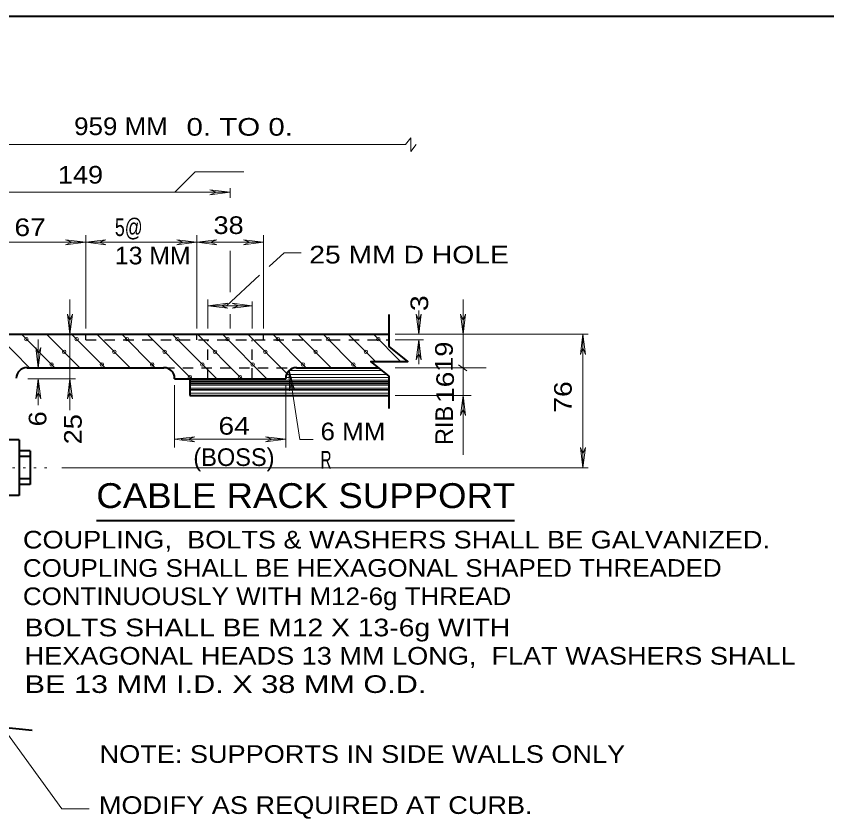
# Model space of a CAD drawing. Extents: x 312583 to 312854, y 144419 to 144597.
# Drawn here: x 312649.47 to 312684.42, y 144454.46 to 144489.05 of the extents above; entities that cross this region are included whole.
import ezdxf
from ezdxf.enums import TextEntityAlignment as Align

# ---------------------------------------------------------------- set-up
doc = ezdxf.new("R2010")
doc.units = 0
doc.header["$LTSCALE"] = 0.3
doc.header["$PDMODE"] = 32
doc.header["$PDSIZE"] = 0.15
doc.linetypes.add('DOTTED', pattern=[1.5, 0.3, -1.2])
doc.linetypes.add('SHORT_DASHED', pattern=[2.7, 1.5, -1.2])
doc.layers.add('1', color=7, linetype='Continuous', lineweight=13)

msp = doc.modelspace()

# ---------------------------------------------------------------- linework, layer by layer
at = {"layer": '1', "lineweight": 40}
for p, q in [((312629.3637, 144489.0473), (312702.1235, 144489.0473)), ((312647.438, 144475.3431), (312665.5544, 144475.3431)), ((312649.9297, 144473.9017), (312655.8407, 144473.9017)), ((312661.5524, 144473.9017), (312665.0867, 144473.9017)), ((312656.3007, 144473.4264), (312656.3007, 144473.4417)), ((312656.3007, 144473.4264), (312661.0924, 144473.4264)), ((312656.96, 144473.4264), (312656.96, 144472.7057)), ((312661.0924, 144473.4264), (312661.0924, 144473.4417)), ((312665.5544, 144472.1461), (312665.5544, 144473.5337)), ((312656.96, 144472.7057), (312665.5544, 144472.7057)), ((312649.5924, 144470.7891), (312649.1094, 144470.7891)), ((312649.5924, 144470.7891), (312649.5924, 144468.3971)), ((312650.0677, 144470.3137), (312649.5924, 144470.3137)), ((312650.0677, 144470.3137), (312650.0677, 144468.8724)), ((312650.0677, 144470.0684), (312649.5924, 144470.0684)), ((312650.0677, 144469.1101), (312649.5924, 144469.1101)), ((312650.0677, 144468.8724), (312649.5924, 144468.8724)), ((312649.5924, 144468.3971), (312649.1094, 144468.3971)), ((312652.935, 144467.3161), (312670.9517, 144467.3161)), ((312650.152, 144458.2617), (312645.9584, 144458.7064))]:
    msp.add_line(p, q, dxfattribs=at)
at = {"layer": '1'}
for p, q in [((312647.438, 144483.5157), (312666.2597, 144483.5157)), ((312657.19, 144482.3351), (312656.3084, 144481.4611)), ((312659.283, 144482.3351), (312657.19, 144482.3351)), ((312647.438, 144481.4611), (312658.6927, 144481.4611)), ((312657.8264, 144481.5684), (312658.1024, 144481.4611)), ((312658.6927, 144481.4611), (312657.8264, 144481.5684)), ((312657.8264, 144481.3537), (312658.1024, 144481.4611)), ((312658.6927, 144481.4611), (312657.8264, 144481.3537)), ((312658.6927, 144481.2157), (312658.6927, 144481.6451)), ((312651.601, 144479.4141), (312651.877, 144479.3067)), ((312652.4674, 144479.3067), (312651.601, 144479.4141)), ((312652.4674, 144475.5884), (312652.4674, 144479.6134)), ((312652.4674, 144479.3067), (312653.3337, 144479.4141)), ((312653.3337, 144479.4141), (312653.0577, 144479.3067)), ((312656.3927, 144479.4141), (312656.6687, 144479.3067)), ((312657.259, 144479.3067), (312656.3927, 144479.4141)), ((312657.259, 144475.5884), (312657.259, 144479.6134)), ((312657.259, 144479.3067), (312658.1254, 144479.4141)), ((312658.1254, 144479.4141), (312657.8494, 144479.3067)), ((312659.2677, 144479.4141), (312659.5437, 144479.3067)), ((312660.134, 144479.3067), (312659.2677, 144479.4141)), ((312660.134, 144475.5884), (312660.134, 144479.6134)), ((312651.601, 144479.1994), (312651.877, 144479.3067)), ((312652.4674, 144479.3067), (312651.601, 144479.1994)), ((312652.4674, 144479.3067), (312653.3337, 144479.1994)), ((312653.3337, 144479.1994), (312653.0577, 144479.3067)), ((312656.3927, 144479.1994), (312656.6687, 144479.3067)), ((312657.259, 144479.3067), (312656.3927, 144479.1994)), ((312657.259, 144479.3067), (312660.134, 144479.3067)), ((312657.259, 144479.3067), (312658.1254, 144479.1994)), ((312658.1254, 144479.1994), (312657.8494, 144479.3067)), ((312659.2677, 144479.1994), (312659.5437, 144479.3067)), ((312660.134, 144479.3067), (312659.2677, 144479.1994)), ((312658.6927, 144477.1524), (312658.6927, 144478.9387)), ((312661.0234, 144478.8544), (312660.3794, 144478.2641)), ((312661.7594, 144478.8544), (312661.0234, 144478.8544)), ((312659.9654, 144477.8884), (312658.5317, 144476.5697)), ((312651.785, 144472.0771), (312651.785, 144476.8373)), ((312657.7344, 144475.5884), (312657.7344, 144476.8457)), ((312657.7344, 144476.5697), (312658.6007, 144476.6771)), ((312657.7344, 144476.5697), (312659.651, 144476.5697)), ((312657.7344, 144476.5697), (312658.6007, 144476.4624)), ((312658.6007, 144476.6771), (312658.3247, 144476.5697)), ((312658.6007, 144476.4624), (312658.3247, 144476.5697)), ((312658.7847, 144476.6771), (312659.0607, 144476.5697)), ((312659.651, 144476.5697), (312658.7847, 144476.6771)), ((312658.7847, 144476.4624), (312659.0607, 144476.5697)), ((312659.651, 144476.5697), (312658.7847, 144476.4624)), ((312659.651, 144475.5884), (312659.651, 144476.7537)), ((312651.6777, 144476.2094), (312651.785, 144475.9334)), ((312651.785, 144475.3431), (312651.6777, 144476.2094)), ((312651.8924, 144476.2094), (312651.785, 144475.9334)), ((312651.785, 144475.3431), (312651.8924, 144476.2094)), ((312666.7197, 144476.2094), (312666.827, 144475.9334)), ((312666.827, 144475.3431), (312666.7197, 144476.2094)), ((312666.827, 144476.3704), (312666.827, 144475.3431)), ((312666.9344, 144476.2094), (312666.827, 144475.9334)), ((312666.827, 144475.3431), (312666.9344, 144476.2094)), ((312668.6364, 144476.2094), (312668.7437, 144475.9334)), ((312668.7437, 144475.3431), (312668.6364, 144476.2094)), ((312668.851, 144476.2094), (312668.7437, 144475.9334)), ((312668.7437, 144475.3431), (312668.851, 144476.2094)), ((312658.6927, 144475.5884), (312658.6927, 144476.2017)), ((312648.611, 144475.3431), (312650.0447, 144473.9017)), ((312649.692, 144475.3431), (312651.1334, 144473.9017)), ((312650.7807, 144475.3431), (312652.2144, 144473.9017)), ((312651.8617, 144475.3431), (312653.303, 144473.9017)), ((312652.9504, 144475.3431), (312654.384, 144473.9017)), ((312654.0314, 144475.3431), (312655.465, 144473.9017)), ((312655.1124, 144475.3431), (312657.029, 144473.4264)), ((312656.201, 144475.3431), (312658.1177, 144473.4264)), ((312657.282, 144475.3431), (312659.1987, 144473.4264)), ((312658.3707, 144475.3431), (312660.2797, 144473.4264)), ((312659.4517, 144475.3431), (312661.1384, 144473.6564)), ((312660.5327, 144475.3431), (312661.974, 144473.9017)), ((312661.6214, 144475.3431), (312663.055, 144473.9017)), ((312662.7024, 144475.3431), (312664.1437, 144473.9017)), ((312663.791, 144475.3431), (312664.964, 144474.1701)), ((312664.872, 144475.3431), (312666.045, 144474.1701)), ((312665.8074, 144475.3431), (312674.1334, 144475.3431)), ((312673.911, 144475.3431), (312673.8037, 144474.4767)), ((312673.911, 144475.3431), (312673.911, 144469.5931)), ((312673.911, 144475.3431), (312674.0184, 144474.4767)), ((312650.4204, 144473.9017), (312650.4204, 144475.1131)), ((312665.8074, 144475.1054), (312667.034, 144475.1054)), ((312666.827, 144475.1054), (312666.7197, 144474.2391)), ((312666.827, 144475.1054), (312666.827, 144474.0551)), ((312666.827, 144475.1054), (312666.9344, 144474.2391)), ((312650.313, 144474.7681), (312650.4204, 144474.4921)), ((312650.4204, 144473.9017), (312650.313, 144474.7681)), ((312650.5277, 144474.7681), (312650.4204, 144474.4921)), ((312650.4204, 144473.9017), (312650.5277, 144474.7681)), ((312666.7197, 144474.2391), (312666.827, 144474.5151)), ((312666.9344, 144474.2391), (312666.827, 144474.5151)), ((312673.8037, 144474.4767), (312673.911, 144474.7527)), ((312674.0184, 144474.4767), (312673.911, 144474.7527)), ((312661.238, 144473.7791), (312665.2477, 144473.7791)), ((312661.238, 144473.7791), (312661.261, 144472.9051)), ((312661.238, 144473.7791), (312661.4757, 144472.9357)), ((312665.8074, 144473.9017), (312669.7327, 144473.9017)), ((312668.5444, 144474.0321), (312668.9047, 144473.7714)), ((312649.9757, 144473.4264), (312652.0304, 144473.4264)), ((312650.4204, 144473.4264), (312650.313, 144472.5601)), ((312650.4204, 144472.2917), (312650.4204, 144473.4264)), ((312650.4204, 144473.4264), (312650.5277, 144472.5601)), ((312651.785, 144473.4264), (312651.6777, 144472.5601)), ((312651.785, 144473.4264), (312651.8924, 144472.5601)), ((312661.0924, 144473.4724), (312665.5544, 144473.4724)), ((312661.123, 144473.6104), (312665.4547, 144473.6104)), ((312656.3007, 144473.1504), (312656.3007, 144470.4594)), ((312656.96, 144473.3651), (312665.5544, 144473.3651)), ((312656.96, 144473.3114), (312665.5544, 144473.3114)), ((312656.96, 144473.2501), (312665.5544, 144473.2501)), ((312656.96, 144473.2041), (312665.5544, 144473.2041)), ((312656.96, 144473.1427), (312665.5544, 144473.1427)), ((312661.0924, 144473.1504), (312661.0924, 144470.4594)), ((312661.261, 144472.9051), (312661.33, 144473.1964)), ((312661.4757, 144472.9357), (312661.33, 144473.1964)), ((312650.313, 144472.5601), (312650.4204, 144472.8361)), ((312650.5277, 144472.5601), (312650.4204, 144472.8361)), ((312651.6777, 144472.5601), (312651.785, 144472.8361)), ((312651.8924, 144472.5601), (312651.785, 144472.8361)), ((312656.96, 144473.0201), (312665.5544, 144473.0201)), ((312656.96, 144473.0201), (312665.5544, 144473.0201)), ((312656.96, 144472.9664), (312665.5544, 144472.9664)), ((312656.96, 144472.9357), (312665.5544, 144472.9357)), ((312656.96, 144472.7977), (312665.5544, 144472.7977)), ((312665.8074, 144472.7057), (312669.0964, 144472.7057)), ((312668.7437, 144472.7057), (312668.6364, 144471.8394)), ((312668.7437, 144472.7057), (312668.851, 144471.8394)), ((312668.6364, 144471.8394), (312668.7437, 144472.1154)), ((312668.851, 144471.8394), (312668.7437, 144472.1154)), ((312656.3007, 144470.8197), (312657.167, 144470.9271)), ((312656.3007, 144470.8197), (312657.167, 144470.7124)), ((312656.5872, 144470.8197), (312661.0924, 144470.8197)), ((312657.167, 144470.9271), (312656.891, 144470.8197)), ((312657.167, 144470.7124), (312656.891, 144470.8197)), ((312660.226, 144470.9271), (312660.502, 144470.8197)), ((312661.0924, 144470.8197), (312660.226, 144470.9271)), ((312660.226, 144470.7124), (312660.502, 144470.8197)), ((312661.0924, 144470.8197), (312660.226, 144470.7124)), ((312673.8037, 144470.4594), (312673.911, 144470.1834)), ((312673.911, 144469.5931), (312673.8037, 144470.4594)), ((312674.0184, 144470.4594), (312673.911, 144470.1834)), ((312673.911, 144469.5931), (312674.0184, 144470.4594)), ((312651.4439, 144469.5931), (312674.1334, 144469.5931))]:
    msp.add_line(p, q, dxfattribs=at)
at = {"layer": '1', "linetype": 'SHORT_DASHED', "lineweight": 25}
for p, q in [((312652.4674, 144475.1054), (312652.4674, 144475.3431)), ((312657.259, 144475.1054), (312657.259, 144475.3431)), ((312660.134, 144475.1054), (312660.134, 144475.3431)), ((312652.4674, 144475.1054), (312665.5544, 144475.1054)), ((312657.7344, 144473.4264), (312657.7344, 144475.1054)), ((312659.651, 144473.4264), (312659.651, 144475.1054)), ((312655.8407, 144473.9017), (312661.5524, 144473.9017))]:
    msp.add_line(p, q, dxfattribs=at)
at = {"layer": '1', "linetype": 'DOTTED'}
msp.add_line((312650.796, 144469.5931), (312642.5697, 144469.5931), dxfattribs=at)
at = {"layer": '1'}
for points in [[(312666.2597, 144483.5157), (312666.4897, 144483.8071), (312666.4897, 144483.2244), (312666.7197, 144483.5157)], [(312647.438, 144479.3067), (312652.4674, 144479.3067), (312657.259, 144479.3067)], [(312668.7437, 144476.8381), (312668.7437, 144473.9017), (312668.7437, 144472.7057), (312668.7437, 144470.1451)], [(312661.238, 144473.7791), (312661.7057, 144470.8044), (312662.2807, 144470.8044)], [(312652.6207, 144454.8961), (312651.44, 144454.8961), (312642.999, 144466.5111)]]:
    msp.add_lwpolyline(points, dxfattribs=at)
at = {"layer": '1', "lineweight": 40}
msp.add_lwpolyline([(312665.5544, 144473.5337), (312664.757, 144474.1701), (312666.3517, 144474.1701), (312665.5544, 144474.8141), (312665.5544, 144476.1941)], dxfattribs=at)
for centre, start, end in [((312649.9316, 144473.4456), 90, 180), ((312655.8388, 144473.4456), 0, 90), ((312661.5504, 144473.4456), 90, 180)]:
    msp.add_arc(centre, 0.46, start, end, dxfattribs=at)
at = {"layer": '1'}
for p in [(312649.9067, 144475.1284), (312652.0764, 144475.1284), (312654.246, 144475.1284), (312656.4157, 144475.1284), (312658.5854, 144475.1284), (312660.755, 144475.1284), (312662.917, 144475.1284), (312665.0867, 144475.1284), (312651.5397, 144474.5841), (312653.7017, 144474.5841), (312655.8714, 144474.5841), (312658.041, 144474.5841), (312660.2107, 144474.5841), (312662.3804, 144474.5841), (312664.55, 144474.5841), (312650.9954, 144474.0397), (312653.165, 144474.0397), (312655.3347, 144474.0397), (312657.4967, 144474.0397), (312659.6664, 144474.0397), (312661.836, 144474.0397), (312664.0057, 144474.0397), (312656.96, 144473.4954), (312659.122, 144473.4954)]:
    msp.add_point(p, dxfattribs=at)

# ---------------------------------------------------------------- texts
for s, width, p in [('959 MM', 1.1, (312651.9683, 144483.9249)), ('0. TO 0.', 1.25, (312656.814, 144483.9)), ('149 ', 1.15, (312651.2662, 144481.8349)), ('38 ', 1.15, (312657.9789, 144479.6633)), ('67 ', 1.2, (312649.3929, 144479.574)), ('5@', 0.75, (312653.7265, 144479.5742)), ('13 MM', 1.05, (312653.7265, 144478.3542)), ('25 MM D HOLE', 1.2, (312662.1073, 144478.3934)), ('64 ', 1.2, (312658.1894, 144471.0162)), ('6 MM', 1.1, (312662.5939, 144470.7738)), ('R', 0.65, (312662.5939, 144469.5538)), ('COUPLING,  BOLTS & WASHERS SHALL BE GALVANIZED.', 1.15, (312649.761, 144466.1114)), ('COUPLING SHALL BE HEXAGONAL SHAPED THREADED', 1.1, (312649.761, 144464.8914)), ('CONTINUOUSLY WITH M12-6g THREAD', 1.1, (312649.761, 144463.6714)), ('BOLTS SHALL BE M12 X 13-6g WITH', 1.2, (312649.8318, 144462.326)), ('HEXAGONAL HEADS 13 MM LONG,  FLAT WASHERS SHALL', 1.15, (312649.8318, 144461.106)), ('BE 13 MM I.D. X 38 MM O.D.', 1.3, (312649.8318, 144459.886)), ('NOTE: SUPPORTS IN SIDE WALLS ONLY', 1.15, (312653.0654, 144456.8731)), ('MODIFY AS REQUIRED AT CURB.', 1.15, (312653.0347, 144454.6727))]:
    msp.add_text(s, height=0.76, dxfattribs=dict(at, width=width)).set_placement(p)
for s, width, p in [(' 3 ', 1.2, (312667.2337, 144476.0028)), (' 19 ', 1.15, (312668.297, 144473.3998)), (' 16 ', 1.2, (312668.3462, 144472.0381)), ('76 ', 1.2, (312673.4261, 144471.9604)), ('6 ', 1.15, (312650.77, 144471.3732)), ('25 ', 1.15, (312652.295, 144470.5996))]:
    msp.add_text(s, height=0.76, rotation=90, dxfattribs=dict(at, width=width)).set_placement(p)
msp.add_text('RIB', height=0.76, rotation=90, dxfattribs=at).set_placement((312668.3082, 144470.5667))
msp.add_text('(BOSS)', height=0.76, dxfattribs=at).set_placement((312657.1086, 144469.6668))
at = {"layer": '1', "width": 1.1}
msp.add_text('CABLE RACK SUPPORT', height=1.073, dxfattribs=at).set_placement((312661.9587, 144467.8527), align=Align.CENTER)

doc.saveas('drawing.dxf')
